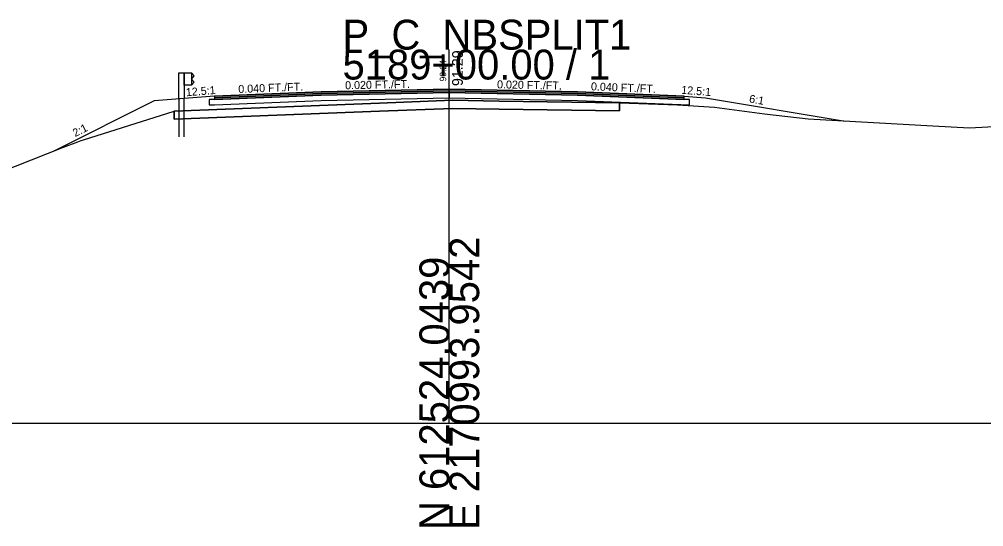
# Model space of a CAD drawing. Extents: x -26 to 1303, y -3010 to 12038.
# Drawn here: x 109.7 to 200.1, y 7990.3 to 8037.8 of the extents above; entities that cross this region are included whole.
import ezdxf

# ---------------------------------------------------------------- set-up
doc = ezdxf.new("R2010")
doc.units = 0
for name, color, linetype in [('RD_GPK_XS_Cell', 7, 'Continuous'), ('RD_PD_Final_TrvlWay', 7, 'Continuous'), ('RD_XS_Base', 7, 'Continuous'), ('RD_XS_ExGround', 7, 'Continuous'), ('RD_XS_ExPaveRet', 7, 'Continuous'), ('RD_XS_GR', 7, 'Continuous'), ('RD_XS_Greenside', 7, 'Continuous'), ('RD_XS_Pave', 7, 'Continuous'), ('RD_XS_PaveOvlay_CP', 7, 'Continuous'), ('RD_XS_TieSlope', 7, 'Continuous'), ('RD_XS_TX_Elev_EX', 7, 'Continuous'), ('RD_XS_TX_Elev_PR', 7, 'Continuous'), ('RD_XS_TX_ShdSlope', 7, 'Continuous'), ('RD_XS_TX_Slope', 7, 'Continuous')]:
    doc.layers.add(name, color=color, linetype=linetype)

msp = doc.modelspace()

# ---------------------------------------------------------------- linework, layer by layer
at = {"layer": 'RD_GPK_XS_Cell'}
for p, q in [((150, 8000), (150, 8035)), ((0, 8000), (150, 8000)), ((150, 8000), (300, 8000))]:
    msp.add_line(p, q, dxfattribs=at)
at = {"layer": 'RD_PD_Final_TrvlWay'}
for p, q in [((125.167, 8030.427), (124.667, 8030.387)), ((124.667, 8030.387), (124.667, 8026.822)), ((125.167, 8026.822), (125.167, 8030.427))]:
    msp.add_line(p, q, dxfattribs=at)
at = {"layer": 'RD_XS_Base'}
for p, q in [((138, 8030.736), (128, 8030.336)), ((150, 8030.976), (138, 8030.736)), ((138, 8030.736), (138, 8030.736)), ((150, 8030.976), (150, 8031.135)), ((150, 8031.135), (150, 8031.135)), ((150, 8031.135), (150, 8031.135)), ((150, 8031.135), (150, 8030.476)), ((150, 8030.476), (150, 8030.976)), ((150, 8030.976), (150, 8030.976)), ((150, 8030.976), (150, 8030.976)), ((150, 8030.976), (150, 8030.976)), ((162, 8030.736), (150, 8030.976)), ((172, 8030.336), (162, 8030.736)), ((164, 8030.656), (164, 8030.656)), ((128, 8030.336), (127.5, 8030.316)), ((127.5, 8030.316), (127.5, 8030.316)), ((127.5, 8030.316), (127.5, 8029.816)), ((127.5, 8029.816), (128, 8029.836)), ((128, 8030.336), (128, 8030.336)), ((128, 8029.836), (138, 8030.236)), ((128, 8029.836), (128, 8029.836)), ((138, 8030.236), (150, 8030.476)), ((138, 8030.236), (138, 8030.236)), ((150, 8030.476), (150, 8030.476)), ((150, 8030.476), (150, 8030.476)), ((150, 8030.476), (162, 8030.236)), ((162, 8030.236), (172.5, 8029.816)), ((164, 8030.156), (164, 8030.156)), ((172.5, 8030.316), (172, 8030.336)), ((172, 8030.336), (172, 8030.336)), ((172.5, 8029.816), (172.5, 8030.316)), ((172.5, 8030.316), (172.5, 8030.316))]:
    msp.add_line(p, q, dxfattribs=at)
at = {"layer": 'RD_XS_ExGround'}
msp.add_lwpolyline([(107.842, 8023.5), (113.848, 8025.857), (115.209, 8026.36), (115.526, 8026.499), (115.717, 8026.563), (124.231, 8029.221), (143.457, 8029.994), (150.295, 8030.25), (154.657, 8030.17), (165.947, 8030.003), (171.386, 8029.814), (174.841, 8029.616), (175.786, 8029.491), (179.541, 8028.976), (183.621, 8028.502), (195.305, 8027.862), (198.73, 8027.662), (201.607, 8027.829)], dxfattribs=at)
at = {"layer": 'RD_XS_ExPaveRet'}
for p, q in [((143.457, 8029.994), (124.231, 8029.221)), ((150.295, 8030.25), (143.457, 8029.994)), ((154.657, 8030.17), (150.295, 8030.25))]:
    msp.add_line(p, q, dxfattribs=at)
for points in [[(165.947, 8030.003), (165.947, 8030.003), (165.947, 8029.252), (165.947, 8029.253), (154.657, 8029.42), (154.657, 8029.42), (150.295, 8029.5), (150.295, 8029.5), (150.295, 8029.5), (143.457, 8029.244), (143.457, 8029.244), (124.231, 8028.471), (124.231, 8028.471), (124.231, 8028.471), (124.231, 8029.221), (124.231, 8029.222), (143.457, 8029.994), (143.457, 8029.994), (150.295, 8030.25), (150.295, 8030.25), (150.295, 8030.25), (154.657, 8030.17), (154.657, 8030.17), (165.947, 8030.003), (165.947, 8030.003)], [(124.231, 8029.221), (124.231, 8028.471), (143.457, 8029.244), (150.295, 8029.5), (154.657, 8029.42), (165.947, 8029.253), (165.947, 8029.252), (165.947, 8030.003)], [(165.947, 8030.003), (165.947, 8030.003), (154.657, 8030.17)]]:
    msp.add_lwpolyline(points, dxfattribs=at)
at = {"layer": 'RD_XS_GR'}
for points in [[(125.167, 8032.822), (125.167, 8030.427), (124.667, 8030.387), (124.667, 8032.822), (124.917, 8032.822), (125.167, 8032.822)], [(125.834, 8032.822), (125.834, 8031.655), (125.167, 8031.655), (125.167, 8032.822), (125.834, 8032.822)], [(125.834, 8032.822), (125.834, 8032.822), (125.834, 8032.822), (125.834, 8031.655), (126.105, 8031.947), (126.105, 8031.947), (125.834, 8032.239), (125.834, 8032.239), (126.105, 8032.53), (126.105, 8032.53), (125.834, 8032.822)]]:
    msp.add_lwpolyline(points, dxfattribs=at)
at = {"layer": 'RD_XS_Greenside'}
for p, q in [((122.355, 8030.202), (113, 8025.524)), ((174, 8030.494), (187.092, 8028.312))]:
    msp.add_line(p, q, dxfattribs=at)
at = {"layer": 'RD_XS_Pave'}
for p, q in [((138, 8031.054), (128, 8030.654)), ((138, 8030.895), (128, 8030.495)), ((128, 8030.495), (138, 8030.895)), ((128, 8030.336), (138, 8030.736)), ((128, 8030.654), (128, 8030.654)), ((128, 8030.654), (128, 8030.495)), ((150, 8031.294), (138, 8031.054)), ((150, 8031.135), (138, 8030.895)), ((138, 8030.895), (150, 8031.135)), ((138, 8031.054), (138, 8031.054)), ((138, 8030.736), (150, 8030.976)), ((138, 8030.895), (138, 8030.895)), ((138, 8030.895), (138, 8030.895)), ((138, 8030.736), (138, 8030.736)), ((162, 8031.054), (150, 8031.294)), ((150, 8031.294), (150, 8031.294)), ((150, 8031.294), (150, 8031.294)), ((150, 8030.976), (150, 8031.135)), ((150, 8031.135), (150, 8031.135)), ((150, 8031.135), (150, 8031.135)), ((150, 8031.135), (150, 8031.135)), ((150, 8031.135), (150, 8031.135)), ((150, 8031.135), (162, 8030.895)), ((162, 8030.895), (150, 8031.135)), ((150, 8031.135), (150, 8031.135)), ((150, 8031.135), (150, 8031.135)), ((150, 8031.135), (150, 8030.976)), ((150, 8030.976), (150, 8030.976)), ((150, 8030.976), (150, 8030.976)), ((150, 8030.976), (162, 8030.736)), ((172, 8030.654), (162, 8031.054)), ((162, 8030.895), (172, 8030.495)), ((172, 8030.495), (162, 8030.895)), ((162, 8030.736), (172, 8030.336)), ((164, 8030.974), (164, 8030.974)), ((164, 8030.815), (164, 8030.815)), ((164, 8030.815), (164, 8030.815)), ((164, 8030.656), (164, 8030.656)), ((172, 8030.495), (172, 8030.654)), ((172, 8030.654), (172, 8030.654)), ((128, 8030.495), (128, 8030.495)), ((128, 8030.495), (128, 8030.336)), ((172, 8030.336), (172, 8030.495)), ((172, 8030.495), (172, 8030.495))]:
    msp.add_line(p, q, dxfattribs=at)
at = {"layer": 'RD_XS_PaveOvlay_CP'}
for p, q in [((128, 8030.654), (138, 8031.054)), ((138, 8031.054), (150, 8031.294)), ((150, 8031.294), (162, 8031.054)), ((162, 8031.054), (172, 8030.654))]:
    msp.add_line(p, q, dxfattribs=at)
at = {"layer": 'RD_XS_TieSlope'}
for p, q in [((128, 8030.654), (122.355, 8030.202)), ((172, 8030.654), (174, 8030.494))]:
    msp.add_line(p, q, dxfattribs=at)

# ---------------------------------------------------------------- texts
at = {"layer": 'RD_GPK_XS_Cell'}
for s, p in [('P_C_NBSPLIT1', (140, 8035)), ('5189+00.00 / 1', (140, 8032.2))]:
    msp.add_text(s, height=2.8, dxfattribs=at).set_placement(p)
for s, p in [('E 2170993.9542', (152.8, 7990)), ('N 612524.0439', (150, 7990))]:
    msp.add_text(s, height=2.8, rotation=90, dxfattribs=at).set_placement(p)
at = {"layer": 'RD_XS_TX_Elev_EX'}
msp.add_text('90.24', height=0.6, rotation=90, dxfattribs=at).set_placement((149.709, 8032.019))
at = {"layer": 'RD_XS_TX_Elev_PR'}
msp.add_text('91.29', height=1, rotation=90, dxfattribs=at).set_placement((151.267, 8031.586))
at = {"layer": 'RD_XS_TX_ShdSlope'}
for rotation, p in [(4.57392, (125.35, 8030.627)), (355.42608, (171.711, 8030.871))]:
    msp.add_text('12.5:1', height=0.75, rotation=rotation, dxfattribs=at).set_placement(p)
at = {"layer": 'RD_XS_TX_Slope'}
for s, rotation, p in [('0.040 FT./FT.', 2.29061, (130.247, 8030.929)), ('0.020 FT./FT.', 1.14576, (140.248, 8031.284)), ('0.020 FT./FT.', 358.85424, (154.468, 8031.375)), ('0.040 FT./FT.', 357.70939, (163.262, 8031.189)), ('6:1', 350.53768, (178.053, 8030.051)), ('2:1', 26.56505, (114.948, 8026.8))]:
    msp.add_text(s, height=0.75, rotation=rotation, dxfattribs=at).set_placement(p)

doc.saveas('drawing.dxf')
